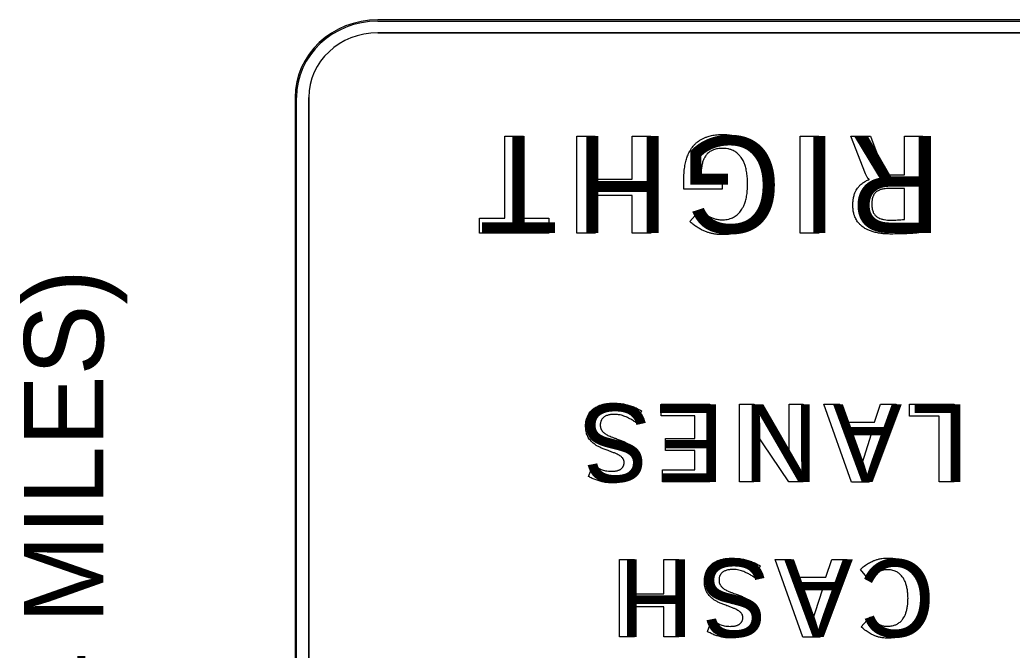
# Model space of a CAD drawing. Extents: x -102643 to -98250, y 54554 to 62384.
# Drawn here: x -102304.2 to -101875.1, y 61646.5 to 61919 of the extents above; entities that cross this region are included whole.
import ezdxf

# ---------------------------------------------------------------- set-up
doc = ezdxf.new("R2010")
doc.units = 0
for name, color, linetype in [('GSBWFill', 7, 'Continuous'), ('GSColorFill', 7, 'Continuous'), ('GSOutline', 7, 'Continuous'), ('SignPanel', 7, 'Continuous'), ('TextLabel', 7, 'Continuous')]:
    doc.layers.add(name, color=color, linetype=linetype)

msp = doc.modelspace()

# ---------------------------------------------------------------- linework, layer by layer
at = {"layer": 'GSBWFill'}
for p, q in [((-101666.66, 61919), (-102149.4, 61919)), ((-102149.4, 61913.42), (-101666.66, 61913.42)), ((-102185.16, 61885.49), (-102185.16, 61433.02)), ((-102179.2, 61433.02), (-102179.2, 61885.49))]:
    msp.add_line(p, q, dxfattribs=at)
for major_axis in [(-35.76, 0), (-29.8, 0)]:
    msp.add_ellipse((-102149.4, 61885.49), major_axis=major_axis, ratio=0.937161, start_param=4.712389, end_param=6.283185, dxfattribs=at)
at = {"layer": 'GSColorFill'}
for p, q in [((-101666.6, 61919), (-102149.4, 61919)), ((-102185.16, 61885.49), (-102185.16, 61433.02))]:
    msp.add_line(p, q, dxfattribs=at)
msp.add_ellipse((-102149.4, 61885.49), major_axis=(-35.76, 0), ratio=0.937161, start_param=4.712389, end_param=6.283185, dxfattribs=at)
at = {"layer": 'GSOutline'}
for p, q in [((-101666.6, 61919), (-102149.4, 61919)), ((-101666.6, 61913.42), (-102149.4, 61913.42)), ((-102185.16, 61885.49), (-102185.16, 61433.02)), ((-102179.2, 61885.49), (-102179.2, 61433.02))]:
    msp.add_line(p, q, dxfattribs=at)
for major_axis in [(-35.76, 0), (-29.8, 0)]:
    msp.add_ellipse((-102149.4, 61885.49), major_axis=major_axis, ratio=0.937161, start_param=4.712389, end_param=6.283185, dxfattribs=at)
at = {"layer": 'SignPanel'}
for p, q in [((-101666.66, 61919), (-102149.4, 61919)), ((-101666.6, 61919), (-102149.4, 61919)), ((-102149.4, 61918.45), (-101666.6, 61918.45)), ((-102149.4, 61913.42), (-101666.66, 61913.42)), ((-102185.16, 61885.49), (-102185.16, 61433.02)), ((-102185.16, 61885.49), (-102185.16, 61433.02)), ((-102184.57, 61433.02), (-102184.57, 61885.49)), ((-102179.2, 61433.02), (-102179.2, 61885.49))]:
    msp.add_line(p, q, dxfattribs=at)
for points in [[(-102094.45, 61833.3), (-102094.45, 61868.73), (-102086.41, 61868.73), (-102086.41, 61833.3), (-102075.51, 61833.3), (-102075.51, 61826.83), (-102105.4, 61826.83), (-102105.4, 61833.3), (-102094.45, 61833.3)], [(-102055.37, 61868.73), (-102055.37, 61850.1), (-102039.45, 61850.1), (-102039.45, 61868.73), (-102031.41, 61868.73), (-102031.41, 61826.83), (-102039.45, 61826.83), (-102039.45, 61843.07), (-102055.37, 61843.07), (-102055.37, 61826.83), (-102063.41, 61826.83), (-102063.41, 61868.73), (-102055.37, 61868.73)], [(-101958.77, 61868.73), (-101958.77, 61826.83), (-101966.81, 61826.83), (-101966.81, 61868.73), (-101958.77, 61868.73)], [(-101938.5, 61852.47), (-101944.84, 61868.73), (-101936.35, 61868.73)], [(-101936.35, 61868.73), (-101930.9, 61854.01)], [(-101928.49, 61852.08), (-101921.75, 61852.08), (-101921.75, 61868.73), (-101913.71, 61868.73), (-101913.71, 61827.1)], [(-102009.62, 61852.08), (-102000.55, 61852.08), (-102000.55, 61845.77), (-102017.07, 61845.77), (-102017.07, 61850.13)], [(-101936.89, 61850), (-101936.89, 61850.08)], [(-101921.75, 61832.69), (-101921.75, 61846.08), (-101928.44, 61846.08)], [(-102014.54, 61831.83), (-102009.94, 61837.02)], [(-102005.88, 61752.82), (-102005.88, 61719.3), (-102026.34, 61719.3), (-102026.34, 61724.44), (-102012.31, 61724.44), (-102012.31, 61732.87), (-102025, 61732.87), (-102025, 61738.04), (-102012.31, 61738.04), (-102012.31, 61747.81), (-102026.89, 61747.81), (-102026.89, 61752.82), (-102005.88, 61752.82)], [(-101986.8, 61752.82), (-101971.68, 61730.36), (-101971.59, 61730.36), (-101971.59, 61752.82), (-101965.46, 61752.82), (-101965.46, 61719.3), (-101971.68, 61719.3), (-101986.71, 61741.53), (-101986.79, 61741.53), (-101986.8, 61719.3), (-101992.97, 61719.3), (-101992.97, 61752.82), (-101986.8, 61752.82)], [(-101949.58, 61752.82), (-101946.97, 61745.16), (-101934.6, 61745.16), (-101931.99, 61752.82), (-101925.27, 61752.82), (-101936.99, 61719.22), (-101944.54, 61719.22), (-101956.51, 61752.82), (-101949.58, 61752.82)], [(-101900.27, 61752.82), (-101900.27, 61719.3), (-101906.7, 61719.3), (-101906.7, 61747.69), (-101919.52, 61747.69), (-101919.52, 61752.82), (-101900.27, 61752.82)], [(-102035.46, 61750.02), (-102037.89, 61745)], [(-101940.85, 61724.92), (-101940.68, 61724.92), (-101935.89, 61740.11), (-101945.64, 61740.11), (-101940.85, 61724.92)], [(-102058.24, 61721.57), (-102056.35, 61726.63)], [(-102038.47, 61685.79), (-102038.47, 61670.88), (-102025.74, 61670.88), (-102025.74, 61685.79), (-102019.31, 61685.79), (-102019.31, 61652.27), (-102025.74, 61652.27), (-102025.74, 61665.26), (-102038.47, 61665.26), (-102038.47, 61652.27), (-102044.9, 61652.27), (-102044.9, 61685.79), (-102038.47, 61685.79)], [(-101970.73, 61685.79), (-101968.12, 61678.13), (-101955.76, 61678.13), (-101953.15, 61685.79), (-101946.43, 61685.79), (-101958.15, 61652.19), (-101965.69, 61652.19), (-101977.67, 61685.79), (-101970.73, 61685.79)], [(-101984.13, 61682.99), (-101986.56, 61677.96)], [(-101937.26, 61677.28), (-101940.69, 61681.47)], [(-101962.01, 61657.89), (-101961.83, 61657.88), (-101957.04, 61673.08), (-101966.8, 61673.08), (-101962.01, 61657.89)], [(-102006.91, 61654.54), (-102005.01, 61659.6)], [(-101940.42, 61656.67), (-101936.6, 61660.83)]]:
    msp.add_lwpolyline(points, dxfattribs=at)
for major_axis in [(-35.76, 0), (-35.76, 0), (-35.17, 0), (-29.8, 0)]:
    msp.add_ellipse((-102149.4, 61885.49), major_axis=major_axis, ratio=0.937161, start_param=4.712389, end_param=6.283185, dxfattribs=at)
for points in [[(-102017.07, 61850.13), (-102017.05, 61850.81), (-102017.03, 61852.79), (-102016.74, 61855.38), (-102016.25, 61857.84), (-102015.68, 61859.82), (-102014.9, 61861.65), (-102014.05, 61863.09), (-102013.41, 61863.98), (-102012.73, 61864.81), (-102011.77, 61865.78), (-102010.46, 61866.79), (-102009.24, 61867.5), (-102008.2, 61868.01), (-102007.07, 61868.47), (-102005.19, 61869.02), (-102002.78, 61869.39), (-102000.99, 61869.43), (-102000.23, 61869.44)], [(-102000.23, 61869.44), (-101999.84, 61869.44), (-101998.7, 61869.42), (-101996.85, 61869.25), (-101994.74, 61868.84), (-101993.1, 61868.32), (-101991.88, 61867.8), (-101990.72, 61867.22), (-101989.35, 61866.4), (-101987.86, 61865.25), (-101986.74, 61864.17), (-101985.72, 61862.98), (-101984.41, 61861.17), (-101983.21, 61858.86), (-101982.33, 61856.36), (-101981.63, 61853.65), (-101981.22, 61850.8), (-101981.18, 61848.62), (-101981.16, 61847.87)], [(-102000.42, 61863.43), (-102000.85, 61863.43), (-102001.48, 61863.41), (-102002.49, 61863.3), (-102003.41, 61863.12), (-102004.26, 61862.84), (-102004.89, 61862.56), (-102005.47, 61862.26), (-102006.13, 61861.82), (-102006.85, 61861.21), (-102007.37, 61860.63), (-102007.73, 61860.13), (-102008.34, 61859.18), (-102008.86, 61857.96), (-102009.3, 61856.14), (-102009.57, 61854.32), (-102009.6, 61852.84), (-102009.62, 61852.08)], [(-101989.53, 61847.82), (-101989.55, 61848.75), (-101989.59, 61850.61), (-101989.87, 61852.92), (-101990.3, 61855.16), (-101990.85, 61856.86), (-101991.51, 61858.23), (-101992.04, 61859.13), (-101992.63, 61859.97), (-101993.47, 61860.88), (-101994.26, 61861.55), (-101994.95, 61862.04), (-101995.69, 61862.49), (-101996.73, 61862.93), (-101998.11, 61863.28), (-101999.37, 61863.42), (-102000.15, 61863.43), (-102000.42, 61863.43)], [(-101936.89, 61850.08), (-101936.91, 61850.09), (-101936.99, 61850.12), (-101937.1, 61850.18), (-101937.24, 61850.27), (-101937.39, 61850.39), (-101937.58, 61850.59), (-101937.74, 61850.83), (-101937.97, 61851.24), (-101938.23, 61851.77), (-101938.41, 61852.25), (-101938.5, 61852.47)], [(-101930.9, 61854.01), (-101930.84, 61853.85), (-101930.71, 61853.48), (-101930.48, 61853.02), (-101930.26, 61852.69), (-101930.12, 61852.54), (-101930.02, 61852.45), (-101929.91, 61852.37), (-101929.75, 61852.29), (-101929.53, 61852.2), (-101929.21, 61852.13), (-101928.84, 61852.09), (-101928.58, 61852.08), (-101928.49, 61852.08)], [(-102000.61, 61832.59), (-102000.34, 61832.59), (-101999.57, 61832.6), (-101998.34, 61832.74), (-101996.98, 61833.07), (-101995.94, 61833.49), (-101995.2, 61833.92), (-101994.5, 61834.38), (-101993.7, 61835.03), (-101992.84, 61835.91), (-101992.23, 61836.72), (-101991.69, 61837.6), (-101991, 61838.93), (-101990.41, 61840.58), (-101989.93, 61842.78), (-101989.6, 61845.06), (-101989.55, 61846.9), (-101989.53, 61847.82)], [(-101981.16, 61847.87), (-101981.18, 61847.13), (-101981.22, 61844.96), (-101981.64, 61842.11), (-101982.36, 61839.4), (-101983.26, 61836.88), (-101984.47, 61834.55), (-101985.82, 61832.74), (-101986.86, 61831.54), (-101987.99, 61830.45), (-101989.5, 61829.28), (-101990.88, 61828.45), (-101992.05, 61827.86), (-101993.28, 61827.32), (-101994.93, 61826.79), (-101997.04, 61826.37), (-101998.89, 61826.19), (-102000.03, 61826.18), (-102000.43, 61826.17)], [(-101944.02, 61838.9), (-101944.01, 61839.24), (-101944, 61840.23), (-101943.82, 61841.8), (-101943.4, 61843.55), (-101942.85, 61844.87), (-101942.3, 61845.83), (-101941.68, 61846.73), (-101940.75, 61847.75), (-101939.37, 61848.8), (-101938.05, 61849.52), (-101937.19, 61849.88), (-101936.89, 61850)], [(-101928.44, 61846.08), (-101928.73, 61846.07), (-101929.55, 61846.06), (-101930.61, 61845.95), (-101931.47, 61845.78), (-101932.03, 61845.62), (-101932.55, 61845.44), (-101933.13, 61845.16), (-101933.57, 61844.88), (-101933.9, 61844.63), (-101934.2, 61844.36), (-101934.55, 61843.97), (-101934.91, 61843.45), (-101935.16, 61842.96), (-101935.33, 61842.55), (-101935.62, 61841.69), (-101935.79, 61840.6), (-101935.81, 61839.63), (-101935.81, 61839.32)], [(-101927.63, 61826.43), (-101928.18, 61826.43), (-101929.8, 61826.46), (-101931.92, 61826.67), (-101933.96, 61827.03), (-101935.64, 61827.45), (-101937.2, 61828.02), (-101938.43, 61828.65), (-101939.2, 61829.12), (-101939.92, 61829.62), (-101940.76, 61830.33), (-101941.65, 61831.29), (-101942.28, 61832.19), (-101942.73, 61832.96), (-101943.14, 61833.79), (-101943.55, 61834.94), (-101943.94, 61836.72), (-101943.99, 61838.06), (-101944.02, 61838.9)], [(-101935.81, 61839.32), (-101935.81, 61839.02), (-101935.79, 61838.18), (-101935.65, 61837.22), (-101935.4, 61836.35), (-101935.2, 61835.81), (-101934.88, 61835.2), (-101934.5, 61834.67), (-101934.13, 61834.28), (-101933.81, 61834), (-101933.46, 61833.75), (-101932.87, 61833.4), (-101931.86, 61832.96), (-101930.43, 61832.6), (-101928.98, 61832.45), (-101928.06, 61832.44), (-101927.73, 61832.43)], [(-102009.94, 61837.02), (-102009.58, 61836.69), (-102008.87, 61836.04), (-102007.78, 61835.15), (-102006.87, 61834.49), (-102006.13, 61834.04), (-102005.57, 61833.73), (-102004.82, 61833.38), (-102004.03, 61833.09), (-102003.22, 61832.87), (-102002.38, 61832.7), (-102001.5, 61832.6), (-102000.83, 61832.59), (-102000.61, 61832.59)], [(-102000.43, 61826.17), (-102000.81, 61826.18), (-102001.93, 61826.19), (-102003.39, 61826.34), (-102004.78, 61826.6), (-102006.07, 61826.92), (-102007.31, 61827.33), (-102008.78, 61827.94), (-102010.16, 61828.64), (-102011.7, 61829.61), (-102013.15, 61830.69), (-102014.08, 61831.45), (-102014.54, 61831.83)], [(-101927.73, 61832.43), (-101927.2, 61832.44), (-101926.18, 61832.44), (-101924.68, 61832.49), (-101923.22, 61832.57), (-101922.24, 61832.65), (-101921.75, 61832.69)], [(-101913.71, 61827.1), (-101914.87, 61826.98), (-101917.18, 61826.76), (-101920.65, 61826.56), (-101924.13, 61826.45), (-101926.46, 61826.43), (-101927.63, 61826.43)], [(-102059.55, 61743.19), (-102059.54, 61743.62), (-102059.52, 61744.64), (-102059.29, 61746.02), (-102058.94, 61747.12), (-102058.65, 61747.78), (-102058.33, 61748.4), (-102057.88, 61749.12), (-102057.25, 61749.91), (-102056.65, 61750.51), (-102056.12, 61750.93), (-102055.57, 61751.33), (-102054.84, 61751.78), (-102053.71, 61752.32), (-102052.48, 61752.72), (-102050.79, 61753.09), (-102049.19, 61753.28), (-102047.96, 61753.3), (-102047.54, 61753.31)], [(-102047.54, 61753.31), (-102046.97, 61753.3), (-102045.32, 61753.27), (-102043.17, 61753), (-102041.14, 61752.52), (-102039.19, 61751.9), (-102037.28, 61751.07), (-102035.92, 61750.29), (-102035.46, 61750.02)], [(-102047.23, 61748.46), (-102047.42, 61748.46), (-102047.98, 61748.45), (-102048.73, 61748.37), (-102049.45, 61748.23), (-102050.14, 61748.06), (-102050.78, 61747.8), (-102051.3, 61747.51), (-102051.64, 61747.27), (-102051.96, 61747.01), (-102052.29, 61746.65), (-102052.54, 61746.32), (-102052.71, 61746.03), (-102052.87, 61745.72), (-102053.03, 61745.29), (-102053.18, 61744.62), (-102053.2, 61744.12), (-102053.21, 61743.8)], [(-102037.89, 61745), (-102038.24, 61745.23), (-102039.28, 61745.94), (-102040.75, 61746.75), (-102042.08, 61747.38), (-102043.05, 61747.77), (-102044.05, 61748.09), (-102045.3, 61748.34), (-102046.36, 61748.45), (-102047.01, 61748.46), (-102047.23, 61748.46)], [(-102049.84, 61732.8), (-102050.41, 61733.01), (-102051.58, 61733.44), (-102053.01, 61734.05), (-102054.41, 61734.73), (-102055.46, 61735.39), (-102056.3, 61736.05), (-102056.87, 61736.55), (-102057.51, 61737.21), (-102058.15, 61738.08), (-102058.62, 61738.89), (-102058.96, 61739.63), (-102059.24, 61740.43), (-102059.5, 61741.68), (-102059.53, 61742.61), (-102059.55, 61743.19)], [(-102053.21, 61743.8), (-102053.21, 61743.7), (-102053.2, 61743.42), (-102053.15, 61742.97), (-102053.02, 61742.45), (-102052.86, 61742.05), (-102052.69, 61741.75), (-102052.51, 61741.47), (-102052.2, 61741.06), (-102051.77, 61740.61), (-102051.28, 61740.22), (-102050.65, 61739.79), (-102049.96, 61739.41), (-102049.02, 61738.98), (-102048, 61738.57), (-102047.16, 61738.28), (-102046.73, 61738.13)], [(-102046.73, 61738.13), (-102046.14, 61737.91), (-102044.95, 61737.47), (-102043.46, 61736.88), (-102042, 61736.22), (-102040.9, 61735.59), (-102040.01, 61734.95), (-102039.41, 61734.46), (-102038.74, 61733.82), (-102038.06, 61732.98), (-102037.56, 61732.19), (-102037.19, 61731.47), (-102036.9, 61730.68), (-102036.67, 61729.64), (-102036.58, 61728.72), (-102036.57, 61728.14), (-102036.57, 61727.94)], [(-102042.91, 61727.69), (-102042.91, 61727.78), (-102042.92, 61728.02), (-102042.98, 61728.41), (-102043.12, 61728.85), (-102043.3, 61729.19), (-102043.48, 61729.44), (-102043.84, 61729.88), (-102044.36, 61730.34), (-102045.02, 61730.78), (-102045.89, 61731.27), (-102047.06, 61731.77), (-102048.53, 61732.31), (-102049.4, 61732.63), (-102049.84, 61732.8)], [(-102048.38, 61723.87), (-102048.02, 61723.87), (-102047.49, 61723.89), (-102046.79, 61723.97), (-102046.29, 61724.04), (-102045.67, 61724.18), (-102045.15, 61724.37), (-102044.74, 61724.58), (-102044.55, 61724.69), (-102044.31, 61724.84), (-102044.03, 61725.06), (-102043.73, 61725.36), (-102043.51, 61725.64), (-102043.35, 61725.88), (-102043.21, 61726.14), (-102043.07, 61726.49), (-102042.96, 61726.94), (-102042.92, 61727.35), (-102042.91, 61727.61), (-102042.91, 61727.69)], [(-102036.57, 61727.94), (-102036.57, 61727.74), (-102036.58, 61727.17), (-102036.67, 61726.25), (-102036.91, 61725.21), (-102037.21, 61724.41), (-102037.51, 61723.82), (-102037.84, 61723.26), (-102038.3, 61722.61), (-102038.94, 61721.9), (-102039.53, 61721.38), (-102040.18, 61720.9), (-102041.15, 61720.3), (-102042.38, 61719.75), (-102043.69, 61719.36), (-102045.06, 61719.06), (-102046.47, 61718.88), (-102047.54, 61718.86), (-102047.9, 61718.86)], [(-102056.35, 61726.63), (-102056.04, 61726.43), (-102055.14, 61725.83), (-102053.89, 61725.15), (-102052.77, 61724.66), (-102051.97, 61724.37), (-102050.95, 61724.09), (-102049.69, 61723.9), (-102048.76, 61723.87), (-102048.38, 61723.87)], [(-102047.9, 61718.86), (-102048.38, 61718.87), (-102049.77, 61718.89), (-102051.59, 61719.13), (-102053.33, 61719.56), (-102055.01, 61720.1), (-102056.66, 61720.76), (-102057.84, 61721.37), (-102058.24, 61721.57)], [(-102008.22, 61676.15), (-102008.21, 61676.59), (-102008.18, 61677.61), (-102007.95, 61678.99), (-102007.6, 61680.08), (-102007.31, 61680.74), (-102007, 61681.36), (-102006.55, 61682.09), (-102005.91, 61682.88), (-102005.31, 61683.47), (-102004.79, 61683.9), (-102004.24, 61684.3), (-102003.5, 61684.75), (-102002.38, 61685.28), (-102001.15, 61685.68), (-101999.45, 61686.06), (-101997.85, 61686.25), (-101996.63, 61686.27), (-101996.21, 61686.28)], [(-101996.21, 61686.28), (-101995.64, 61686.27), (-101993.99, 61686.24), (-101991.84, 61685.97), (-101989.81, 61685.49), (-101987.85, 61684.87), (-101985.94, 61684.04), (-101984.59, 61683.26), (-101984.13, 61682.99)], [(-101940.69, 61681.47), (-101940.27, 61681.84), (-101939.06, 61682.94), (-101937.25, 61684.15), (-101935.56, 61684.99), (-101934.32, 61685.49), (-101933.02, 61685.89), (-101931.39, 61686.21), (-101929.98, 61686.34), (-101929.11, 61686.35), (-101928.82, 61686.36)], [(-101928.82, 61686.36), (-101928.17, 61686.34), (-101927.21, 61686.32), (-101925.67, 61686.15), (-101924.24, 61685.89), (-101922.88, 61685.47), (-101921.88, 61685.06), (-101920.95, 61684.6), (-101919.84, 61683.95), (-101918.64, 61683.04), (-101917.75, 61682.17), (-101917.1, 61681.42), (-101916.5, 61680.62), (-101915.67, 61679.32), (-101914.9, 61677.67), (-101914.33, 61675.89), (-101913.82, 61673.68), (-101913.52, 61671.36), (-101913.49, 61669.58), (-101913.48, 61668.97)], [(-101995.9, 61681.43), (-101996.09, 61681.43), (-101996.65, 61681.42), (-101997.39, 61681.34), (-101998.11, 61681.2), (-101998.8, 61681.02), (-101999.45, 61680.77), (-101999.96, 61680.47), (-102000.31, 61680.24), (-102000.62, 61679.98), (-102000.96, 61679.62), (-102001.2, 61679.28), (-102001.38, 61679), (-102001.54, 61678.69), (-102001.69, 61678.26), (-102001.85, 61677.59), (-102001.86, 61677.08), (-102001.87, 61676.77)], [(-101986.56, 61677.96), (-101986.91, 61678.2), (-101987.94, 61678.9), (-101989.42, 61679.72), (-101990.74, 61680.34), (-101991.71, 61680.74), (-101992.72, 61681.06), (-101993.96, 61681.31), (-101995.03, 61681.42), (-101995.68, 61681.43), (-101995.9, 61681.43)], [(-101929, 61681.27), (-101929.2, 61681.26), (-101929.79, 61681.25), (-101930.74, 61681.15), (-101931.84, 61680.9), (-101932.7, 61680.59), (-101933.52, 61680.2), (-101934.71, 61679.5), (-101936.02, 61678.48), (-101936.93, 61677.6), (-101937.26, 61677.28)], [(-101920.17, 61668.97), (-101920.2, 61669.73), (-101920.24, 61671.24), (-101920.51, 61673.1), (-101920.91, 61674.87), (-101921.4, 61676.2), (-101921.96, 61677.27), (-101922.4, 61677.98), (-101922.89, 61678.63), (-101923.57, 61679.34), (-101924.21, 61679.85), (-101924.76, 61680.22), (-101925.35, 61680.55), (-101926.16, 61680.88), (-101927.24, 61681.15), (-101928.2, 61681.25), (-101928.79, 61681.26), (-101929, 61681.27)], [(-101998.5, 61665.76), (-101999.08, 61665.98), (-102000.24, 61666.41), (-102001.67, 61667.01), (-102003.08, 61667.7), (-102004.12, 61668.36), (-102004.97, 61669.01), (-102005.53, 61669.52), (-102006.17, 61670.18), (-102006.82, 61671.05), (-102007.28, 61671.86), (-102007.63, 61672.59), (-102007.9, 61673.4), (-102008.17, 61674.64), (-102008.2, 61675.57), (-102008.22, 61676.15)], [(-102001.87, 61676.77), (-102001.87, 61676.67), (-102001.87, 61676.39), (-102001.81, 61675.94), (-102001.69, 61675.42), (-102001.52, 61675.02), (-102001.36, 61674.72), (-102001.18, 61674.43), (-102000.87, 61674.02), (-102000.44, 61673.58), (-101999.94, 61673.19), (-101999.31, 61672.76), (-101998.62, 61672.37), (-101997.68, 61671.94), (-101996.67, 61671.53), (-101995.83, 61671.25), (-101995.4, 61671.1)], [(-101995.4, 61671.1), (-101994.81, 61670.88), (-101993.61, 61670.43), (-101992.13, 61669.84), (-101990.66, 61669.19), (-101989.57, 61668.55), (-101988.68, 61667.91), (-101988.08, 61667.43), (-101987.41, 61666.79), (-101986.73, 61665.94), (-101986.23, 61665.15), (-101985.86, 61664.44), (-101985.57, 61663.64), (-101985.34, 61662.61), (-101985.24, 61661.68), (-101985.23, 61661.11), (-101985.23, 61660.91)], [(-101929, 61656.87), (-101928.81, 61656.88), (-101928.29, 61656.88), (-101927.43, 61656.97), (-101926.46, 61657.17), (-101925.7, 61657.43), (-101925.14, 61657.69), (-101924.6, 61657.98), (-101923.97, 61658.4), (-101923.28, 61659), (-101922.76, 61659.57), (-101922.38, 61660.07), (-101921.73, 61661.05), (-101921.15, 61662.34), (-101920.71, 61663.89), (-101920.38, 61665.49), (-101920.2, 61667.19), (-101920.18, 61668.51), (-101920.17, 61668.97)], [(-101913.48, 61668.97), (-101913.49, 61668.39), (-101913.53, 61666.71), (-101913.84, 61664.49), (-101914.37, 61662.37), (-101915.04, 61660.38), (-101915.97, 61658.53), (-101917.01, 61657.08), (-101917.82, 61656.12), (-101918.71, 61655.23), (-101919.91, 61654.28), (-101921.01, 61653.61), (-101921.95, 61653.12), (-101922.95, 61652.68), (-101924.3, 61652.24), (-101926.03, 61651.9), (-101927.57, 61651.76), (-101928.52, 61651.75), (-101928.85, 61651.74)], [(-101991.58, 61660.66), (-101991.58, 61660.74), (-101991.58, 61660.98), (-101991.64, 61661.37), (-101991.79, 61661.82), (-101991.97, 61662.16), (-101992.15, 61662.41), (-101992.51, 61662.85), (-101993.02, 61663.31), (-101993.69, 61663.74), (-101994.56, 61664.24), (-101995.73, 61664.74), (-101997.19, 61665.27), (-101998.06, 61665.6), (-101998.5, 61665.76)], [(-102005.01, 61659.6), (-102004.7, 61659.39), (-102003.81, 61658.8), (-102002.56, 61658.12), (-102001.44, 61657.63), (-102000.64, 61657.34), (-101999.62, 61657.05), (-101998.35, 61656.86), (-101997.43, 61656.84), (-101997.04, 61656.83)], [(-101997.04, 61656.83), (-101996.68, 61656.84), (-101996.15, 61656.85), (-101995.46, 61656.93), (-101994.96, 61657.01), (-101994.33, 61657.15), (-101993.82, 61657.34), (-101993.41, 61657.54), (-101993.22, 61657.65), (-101992.98, 61657.81), (-101992.69, 61658.03), (-101992.39, 61658.33), (-101992.17, 61658.61), (-101992.02, 61658.85), (-101991.88, 61659.1), (-101991.74, 61659.45), (-101991.63, 61659.91), (-101991.58, 61660.32), (-101991.58, 61660.57), (-101991.58, 61660.66)], [(-101985.23, 61660.91), (-101985.23, 61660.71), (-101985.24, 61660.14), (-101985.34, 61659.22), (-101985.57, 61658.18), (-101985.87, 61657.38), (-101986.17, 61656.78), (-101986.5, 61656.23), (-101986.96, 61655.58), (-101987.6, 61654.87), (-101988.2, 61654.34), (-101988.85, 61653.87), (-101989.82, 61653.26), (-101991.04, 61652.72), (-101992.35, 61652.33), (-101993.72, 61652.03), (-101995.14, 61651.85), (-101996.21, 61651.83), (-101996.57, 61651.82)], [(-101936.6, 61660.83), (-101936.31, 61660.52), (-101935.75, 61659.93), (-101935.02, 61659.25), (-101934.29, 61658.65), (-101933.7, 61658.23), (-101933.09, 61657.87), (-101932.48, 61657.56), (-101931.84, 61657.31), (-101931.17, 61657.12), (-101930.48, 61656.97), (-101929.75, 61656.88), (-101929.19, 61656.88), (-101929, 61656.87)], [(-101996.57, 61651.82), (-101997.05, 61651.83), (-101998.43, 61651.86), (-102000.25, 61652.1), (-102001.99, 61652.53), (-102003.67, 61653.06), (-102005.32, 61653.73), (-102006.51, 61654.33), (-102006.91, 61654.54)], [(-101928.85, 61651.74), (-101929.14, 61651.75), (-101929.98, 61651.76), (-101931.35, 61651.88), (-101932.92, 61652.19), (-101934.15, 61652.57), (-101935.33, 61653.06), (-101936.97, 61653.91), (-101938.77, 61655.16), (-101939.99, 61656.28), (-101940.42, 61656.67)]]:
    msp.add_open_spline(points, degree=3, dxfattribs=at)

# ---------------------------------------------------------------- texts
for s, height, p in [('T', 41.89, (-102071.47, 61868.73)), ('T', 41.89, (-102071.47, 61868.73)), ('H', 41.89, (-102023.37, 61868.73)), ('H', 41.89, (-102023.37, 61868.73)), ('G', 41.89, (-101974.91, 61868.73)), ('G', 41.89, (-101974.91, 61868.73)), ('I', 41.89, (-101950.73, 61868.73)), ('I', 41.89, (-101950.73, 61868.73)), ('R', 41.89, (-101905.67, 61868.73)), ('R', 41.89, (-101905.67, 61868.73)), ('S', 33.52, (-102031.53, 61752.82)), ('S', 33.52, (-102031.53, 61752.82)), ('E', 33.52, (-101999.45, 61752.82)), ('E', 33.52, (-101999.45, 61752.82)), ('N', 33.52, (-101959.03, 61752.82)), ('N', 33.52, (-101959.03, 61752.82)), ('A', 33.52, (-101922.77, 61752.82)), ('A', 33.52, (-101922.77, 61752.82)), ('L', 33.52, (-101893.84, 61752.82)), ('L', 33.52, (-101893.84, 61752.82)), ('H', 33.52, (-102012.88, 61685.79)), ('H', 33.52, (-102012.88, 61685.79)), ('S', 33.52, (-101980.19, 61685.79)), ('S', 33.52, (-101980.19, 61685.79)), ('A', 33.52, (-101943.93, 61685.79)), ('A', 33.52, (-101943.93, 61685.79)), ('C', 33.52, (-101908.49, 61685.79)), ('C', 33.52, (-101908.49, 61685.79))]:
    msp.add_text(s, height=height, rotation=180, dxfattribs=at).set_placement(p)
at = {"layer": 'TextLabel'}
msp.add_text('(1 TO 1-1/4 MILES)', height=34.335, rotation=90, dxfattribs=at).set_placement((-102268, 61410.62))

doc.saveas('drawing.dxf')
